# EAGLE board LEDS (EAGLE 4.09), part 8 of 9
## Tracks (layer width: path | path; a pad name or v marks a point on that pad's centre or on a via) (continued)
N$X.3143  (via drill 0.2)  (1 unrouted) (continued)
  other vias: 92.89,75.03
N$X.3144  (via drill 0.2)  (1 unrouted)
  Bottom 0.2: 94.72,74.97 94.18,75.51 93.83,75.51
  other vias: 94.68,74.95
N$X.3145  (via drill 0.2)  (1 unrouted)
  Bottom 0.2: 96.47,75 95.92,75.54 95.57,75.54
  other vias: 96.42,74.98
N$X.3146  (via drill 0.2)  (1 unrouted)
  Bottom 0.2: 98.2,75.05 97.66,75.6 97.31,75.6
  other vias: 98.16,75.03
N$X.3147  (via drill 0.2)  (1 unrouted)
  Bottom 0.2: 99.97,75.02 99.42,75.57 99.08,75.57
  other vias: 99.92,75
N$X.3148  (via drill 0.2)  (1 unrouted)
  Bottom 0.2: 101.63,75.02 101.08,75.57 100.73,75.57
  other vias: 101.58,75
N$X.3149  (via drill 0.2)  (1 unrouted)
  Bottom 0.2: 103.39,75 102.85,75.54 102.5,75.54
  other vias: 103.35,74.98
N$X.3150  (via drill 0.2)  (1 unrouted)
  Bottom 0.2: 105.25,75.02 104.7,75.57 104.35,75.57
  other vias: 105.2,75
N$X.3151  (via drill 0.2)  (1 unrouted)
  Bottom 0.2: 106.93,75.02 106.39,75.57 106.03,75.57
  other vias: 106.89,75
N$X.3152  (via drill 0.2)  (1 unrouted)
  Bottom 0.2: 106.84,72.48 106.3,73.03 105.95,73.03
  other vias: 106.8,72.46
N$X.3153  (via drill 0.2)  (1 unrouted)
  Bottom 0.2: 105.11,72.48 104.56,73.03 104.21,73.03
  other vias: 105.06,72.46
N$X.3154  (via drill 0.2)  (1 unrouted)
  Bottom 0.2: 103.48,72.46 102.94,73 102.58,73
  other vias: 103.44,72.44
N$X.3155  (via drill 0.2)  (1 unrouted)
  Bottom 0.2: 101.63,72.4 101.08,72.95 100.73,72.95
  other vias: 101.67,72.42
N$X.3156  (via drill 0.2)  (1 unrouted)
  Bottom 0.2: 99.97,72.46 99.42,73 99.08,73
  other vias: 99.92,72.44
N$X.3157  (via drill 0.2)  (1 unrouted)
  Bottom 0.2: 98.23,72.43 97.69,72.97 97.33,72.97
  other vias: 98.19,72.41
N$X.3158  (via drill 0.2)  (1 unrouted)
  Bottom 0.2: 96.41,72.4 95.86,72.95 95.52,72.95
  other vias: 96.47,72.42
N$X.3159  (via drill 0.2)  (1 unrouted)
  Bottom 0.2: 94.7,72.43 94.16,72.97 93.8,72.97
  other vias: 94.66,72.41
N$X.3160  (via drill 0.2)  (1 unrouted)
  Bottom 0.2: 93.04,72.4 92.5,72.95 92.14,72.95
  other vias: 93,72.38
N$X.3161  (via drill 0.2)  (1 unrouted)
  Bottom 0.2: 91.19,72.37 90.64,72.92 90.3,72.92
  other vias: 91.21,72.39
N$X.3162  (via drill 0.2)  (1 unrouted)
  Bottom 0.2: 89.48,72.4 88.94,72.95 88.58,72.95
  other vias: 89.44,72.38
N$X.3163  (via drill 0.2)  (1 unrouted)
  Bottom 0.2: 87.63,72.4 87.08,72.95 86.73,72.95
  other vias: 87.65,72.42
N$X.3164  (via drill 0.2)  (1 unrouted)
  Bottom 0.2: 85.94,72.43 85.4,72.97 85.05,72.97
  other vias: 85.9,72.41
N$X.3165  (via drill 0.2)  (1 unrouted)
  Bottom 0.2: v84.18,72.4 83.64,72.95 83.28,72.95
N$X.3166  (via drill 0.2)  (1 unrouted)
  Bottom 0.2: 84.18,69.81 83.64,70.35 83.28,70.35
  other vias: 84.14,69.79
N$X.3167  (via drill 0.2)  (1 unrouted)
  Bottom 0.2: 85.89,69.83 85.34,70.38 85,70.38
  other vias: 85.84,69.81
N$X.3168  (via drill 0.2)  (1 unrouted)
  Bottom 0.2: 87.69,69.83 87.14,70.38 86.79,70.38
  other vias: 87.64,69.81
N$X.3169  (via drill 0.2)  (1 unrouted)
  Bottom 0.2: 89.45,69.86 88.91,70.41 88.55,70.41
  other vias: 89.41,69.84
N$X.3170  (via drill 0.2)  (1 unrouted)
  Bottom 0.2: 91.16,69.78 90.62,70.32 90.27,70.32
  other vias: 91.18,69.8
N$X.3171  (via drill 0.2)  (1 unrouted)
  Bottom 0.2: 93.04,69.83 92.5,70.38 92.14,70.38
  other vias: 93,69.81
N$X.3172  (via drill 0.2)  (1 unrouted)
  Bottom 0.2: 94.78,69.83 94.23,70.38 93.89,70.38
  other vias: 94.73,69.81
N$X.3173  (via drill 0.2)  (1 unrouted)
  Bottom 0.2: 96.49,69.86 95.94,70.41 95.59,70.41
  other vias: 96.44,69.84
N$X.3174  (via drill 0.2)  (1 unrouted)
  Bottom 0.2: 98.28,69.83 97.74,70.38 97.39,70.38
  other vias: 98.24,69.81
N$X.3175  (via drill 0.2)  (1 unrouted)
  Bottom 0.2: 100.05,69.89 99.51,70.43 99.16,70.43
  other vias: 99.99,69.83
N$X.3176  (via drill 0.2)  (1 unrouted)
  Bottom 0.2: 101.63,69.92 101.08,70.46 100.73,70.46
  other vias: 101.63,69.81
N$X.3177  (via drill 0.2)  (1 unrouted)
  Bottom 0.2: 103.42,69.86 102.88,70.41 102.53,70.41
  other vias: 103.38,69.84
N$X.3178  (via drill 0.2)  (1 unrouted)
  Bottom 0.2: 105.3,69.83 104.75,70.38 104.41,70.38
  other vias: 105.17,69.83
N$X.3179  (via drill 0.2)  (1 unrouted)
  Bottom 0.2: 106.9,69.86 106.36,70.41 106,70.41
  other vias: 106.86,69.84
N$X.3180  (via drill 0.2)  (1 unrouted)
  Bottom 0.2: 106.93,67.18 106.39,67.73 106.03,67.73
  other vias: 106.89,67.16
N$X.3181  (via drill 0.2)  (1 unrouted)
  Bottom 0.2: 105.19,67.24 104.64,67.78 104.3,67.78
  other vias: 105.14,67.22
N$X.3182  (via drill 0.2)  (1 unrouted)
  Bottom 0.2: 103.5,67.24 102.96,67.78 102.61,67.78
  other vias: 103.46,67.17
N$X.3183  (via drill 0.2)  (1 unrouted)
  Bottom 0.2: 101.74,67.18 101.19,67.73 100.84,67.73
  other vias: 101.69,67.16
N$X.3184  (via drill 0.2)  (1 unrouted)
  Bottom 0.2: 100,67.18 99.45,67.73 99.11,67.73
  other vias: 99.95,67.16
N$X.3185  (via drill 0.2)  (1 unrouted)
  Bottom 0.2: 98.26,67.21 97.72,67.76 97.36,67.76
  other vias: 98.22,67.19
N$X.3186  (via drill 0.2)  (1 unrouted)
  Bottom 0.2: 96.47,67.24 95.92,67.78 95.57,67.78
  other vias: 96.42,67.22
N$X.3187  (via drill 0.2)  (1 unrouted)
  Bottom 0.2: 94.7,67.24 94.16,67.78 93.8,67.78
  other vias: 94.66,67.22
N$X.3188  (via drill 0.2)  (1 unrouted)
  Bottom 0.2: 92.96,67.21 92.41,67.76 92.06,67.76
  other vias: 92.91,67.19
N$X.3189  (via drill 0.2)  (1 unrouted)
  Bottom 0.2: 91.19,67.21 90.64,67.76 90.3,67.76
  other vias: 91.14,67.19
N$X.3190  (via drill 0.2)  (1 unrouted)
  Bottom 0.2: 89.48,67.21 88.94,67.76 88.58,67.76
  other vias: 89.44,67.19
N$X.3191  (via drill 0.2)  (1 unrouted)
  Bottom 0.2: 87.69,67.24 87.14,67.78 86.79,67.78
  other vias: 87.64,67.22
N$X.3192  (via drill 0.2)  (1 unrouted)
  Bottom 0.2: 85.97,67.21 85.43,67.76 85.08,67.76
  other vias: 85.93,67.19
N$X.3193  (via drill 0.2)  (1 unrouted)
  Bottom 0.2: 84.23,67.27 83.69,67.81 83.34,67.81
  other vias: 84.19,67.2
N$X.3194  (via drill 0.2)  (1 unrouted)
  Bottom 0.2: 84.23,64.62 83.69,65.16 83.34,65.16
  other vias: 84.19,64.6
N$X.3195  (via drill 0.2)  (1 unrouted)
  Bottom 0.2: 85.89,64.64 85.34,65.19 85,65.19
  other vias: 85.84,64.62
N$X.3196  (via drill 0.2)  (1 unrouted)
  Bottom 0.2: 87.77,64.59 87.22,65.13 86.87,65.13
  other vias: 87.72,64.57
N$X.3197  (via drill 0.2)  (1 unrouted)
  Bottom 0.2: 89.42,64.64 88.88,65.19 88.53,65.19
  other vias: 89.38,64.62
N$X.3198  (via drill 0.2)  (1 unrouted)
  Bottom 0.2: 91.28,64.62 90.73,65.16 90.38,65.16
  other vias: 91.23,64.6
N$X.3199  (via drill 0.2)  (1 unrouted)
  Bottom 0.2: 92.93,64.67 92.39,65.22 92.03,65.22
  other vias: 92.89,64.65
N$X.3200  (via drill 0.2)  (1 unrouted)
  Bottom 0.2: 94.72,64.59 94.18,65.13 93.83,65.13
  other vias: 94.68,64.57
N$X.3201  (via drill 0.2)  (1 unrouted)
  Bottom 0.2: 96.44,64.59 95.89,65.13 95.54,65.13
  other vias: 96.39,64.57
N$X.3202  (via drill 0.2)  (1 unrouted)
  Bottom 0.2: 98.26,64.59 97.72,65.13 97.36,65.13
  other vias: 98.22,64.57
N$X.3203  (via drill 0.2)  (1 unrouted)
  Bottom 0.2: 99.97,64.67 99.42,65.22 99.08,65.22
  other vias: 99.95,64.57
N$X.3204  (via drill 0.2)  (1 unrouted)
  Bottom 0.2: 101.69,64.64 101.14,65.19 100.79,65.19
  other vias: 101.66,64.58
N$X.3205  (via drill 0.2)  (1 unrouted)
  Bottom 0.2: 103.45,64.64 102.91,65.19 102.55,65.19
  other vias: 103.36,64.56
N$X.3206  (via drill 0.2)  (1 unrouted)
  Bottom 0.2: 105.16,64.64 104.61,65.19 104.27,65.19
  other vias: 105.11,64.54
N$X.3207  (via drill 0.2)  (1 unrouted)
  Bottom 0.2: 106.9,64.59 106.36,65.13 106,65.13
  other vias: 106.86,64.57
N$X.3208  (via drill 0.2)  (1 unrouted)
  Bottom 0.2: 106.9,61.94 106.36,62.48 106,62.48
  other vias: 106.86,61.92
N$X.3209  (via drill 0.2)  (1 unrouted)
  Bottom 0.2: 105.22,61.99 104.67,62.54 104.32,62.54
  other vias: 105.17,61.97
N$X.3210  (via drill 0.2)  (1 unrouted)
  Bottom 0.2: 103.42,61.96 102.88,62.51 102.53,62.51
  other vias: 103.38,61.94
N$X.3211  (via drill 0.2)  (1 unrouted)
  Bottom 0.2: 101.6,61.99 101.05,62.54 100.7,62.54
  other vias: 101.55,61.97
N$X.3212  (via drill 0.2)  (1 unrouted)
  Bottom 0.2: 99.91,61.96 99.37,62.51 99.02,62.51
  other vias: 99.87,61.94
N$X.3213  (via drill 0.2)  (1 unrouted)
  Bottom 0.2: 98.23,61.96 97.69,62.51 97.33,62.51
  other vias: 98.19,61.94
N$X.3214  (via drill 0.2)  (1 unrouted)
  Bottom 0.2: 96.49,62.02 95.94,62.56 95.59,62.56
  other vias: 96.44,61.95
N$X.3215  (via drill 0.2)  (1 unrouted)
  Bottom 0.2: 94.72,62.02 94.18,62.56 93.83,62.56
  other vias: 94.72,61.91
N$X.3216  (via drill 0.2)  (1 unrouted)
  Bottom 0.2: 92.98,62.05 92.44,62.59 92.09,62.59
  other vias: 92.94,61.97
N$X.3217  (via drill 0.2)  (1 unrouted)
  Bottom 0.2: 91.22,61.94 90.67,62.48 90.33,62.48
  other vias: 91.17,61.92
N$X.3218  (via drill 0.2)  (1 unrouted)
  Bottom 0.2: 89.5,62.05 88.96,62.59 88.61,62.59
  other vias: 89.41,61.97
N$X.3219  (via drill 0.2)  (1 unrouted)
  Bottom 0.2: 87.63,62.02 87.08,62.56 86.73,62.56
  other vias: 87.58,62
N$X.3220  (via drill 0.2)  (1 unrouted)
  Bottom 0.2: 85.89,62.02 85.34,62.56 85,62.56
  other vias: 85.89,61.95
N$X.3221  (via drill 0.2)  (1 unrouted)
  Bottom 0.2: 84.18,61.96 83.64,62.51 83.28,62.51
  other vias: 84.14,61.94
N$X.3222  (via drill 0.2)  (1 unrouted)
  Bottom 0.2: 108.64,75.05 108.09,75.6 107.75,75.6
  other vias: 108.59,75.03
N$X.3223  (via drill 0.2)  (1 unrouted)
  Bottom 0.2: 108.67,72.46 108.12,73 107.78,73
  other vias: 108.62,72.44
N$X.3224  (via drill 0.2)  (1 unrouted)
  Bottom 0.2: 108.64,69.94 108.09,70.49 107.75,70.49
  other vias: 108.59,69.92
N$X.3225  (via drill 0.2)  (1 unrouted)
  Bottom 0.2: 108.64,67.27 108.09,67.81 107.75,67.81
  other vias: 108.59,67.25
N$X.3226  (via drill 0.2)  (1 unrouted)
  Bottom 0.2: 108.61,64.59 108.07,65.13 107.72,65.13
  other vias: 108.57,64.57
N$X.3227  (via drill 0.2)  (1 unrouted)
  Bottom 0.2: 108.67,61.99 108.12,62.54 107.78,62.54
  other vias: 108.62,61.97
N$X.3228  (via drill 0.2)  (1 unrouted)
  Bottom 0.2: 110.38,61.99 109.83,62.54 109.48,62.54
  other vias: 110.36,61.93
N$X.3229  (via drill 0.2)  (1 unrouted)
  Bottom 0.2: 110.36,64.64 109.81,65.19 109.46,65.19
  other vias: 110.35,64.54
N$X.3230  (via drill 0.2)  (1 unrouted)
  Bottom 0.2: 110.38,67.29 109.83,67.84 109.48,67.84
  other vias: 110.33,67.21
N$X.3231  (via drill 0.2)  (1 unrouted)
  Bottom 0.2: 110.33,69.92 109.78,70.46 109.43,70.46
  other vias: 110.28,69.9
N$X.3232  (via drill 0.2)  (1 unrouted)
  Bottom 0.2: 110.36,72.51 109.81,73.06 109.46,73.06
  other vias: 110.31,72.49
N$X.3233  (via drill 0.2)  (1 unrouted)
  Bottom 0.2: 110.41,75.11 109.86,75.65 109.52,75.65
  other vias: 110.36,75
N$X.3234  (via drill 0.2)  (1 unrouted)
  Bottom 0.2: 112.12,75.05 111.58,75.6 111.22,75.6
  other vias: 112.08,75.03
N$X.3235  (via drill 0.2)  (1 unrouted)
  Bottom 0.2: 112.14,72.51 111.6,73.06 111.25,73.06
  other vias: 112.1,72.49
N$X.3236  (via drill 0.2)  (1 unrouted)
  Bottom 0.2: 112.06,69.78 111.52,70.32 111.17,70.32
  other vias: 112.02,69.76
N$X.3237  (via drill 0.2)  (1 unrouted)
  Bottom 0.2: 112.12,67.27 111.58,67.81 111.22,67.81
  other vias: 112.08,67.25
N$X.3238  (via drill 0.2)  (1 unrouted)
  Bottom 0.2: 112.12,64.59 111.58,65.13 111.22,65.13
  other vias: 112.08,64.57
N$X.3239  (via drill 0.2)  (1 unrouted)
  Bottom 0.2: 112.23,61.96 111.69,62.51 111.33,62.51
  other vias: 112.19,61.94
N$X.3242  (via drill 0.2)  (1 unrouted)
  Bottom 0.2: 113.95,67.19 113.67,67.92 113.33,67.92
  other vias: 113.96,67.17
N$X.3246  (via drill 0.2)  (1 unrouted)
  Bottom 0.2: 19.4,72.48 18.86,73.03 18.51,73.03
  other vias: 19.36,72.46
N$X.3247  (via drill 0.2)  (1 unrouted)
  Bottom 0.2: 17.63,72.46 17.09,73 16.74,73
  other vias: 17.59,72.44
N$X.3248  (via drill 0.2)  (1 unrouted)
  Bottom 0.2: 15.87,72.46 15.33,73 14.98,73
  other vias: 15.83,72.44
N$X.3249  (via drill 0.2)  (1 unrouted)
  Bottom 0.2: 14.16,72.4 13.62,72.95 13.27,72.95
  other vias: 14.12,72.38
N$X.3250  (via drill 0.2)  (1 unrouted)
  Bottom 0.2: 12.31,72.48 11.77,73.03 11.42,73.03
  other vias: 12.27,72.46
N$X.3251  (via drill 0.2)  (1 unrouted)
  Bottom 0.2: 10.6,72.4 10.05,72.95 9.7,72.95
  other vias: 10.55,72.38
N$X.3252  (via drill 0.2)  (1 unrouted)
  Bottom 0.2: 8.83,72.4 8.29,72.95 7.93,72.95
  other vias: 8.85,72.42
N$X.3253  (via drill 0.2)  (1 unrouted)
  Bottom 0.2: 7.04,72.46 6.49,73 6.14,73
  other vias: 6.99,72.44
N$X.3254  (via drill 0.2)  (1 unrouted)
  Bottom 0.2: 5.35,72.43 4.8,72.97 4.46,72.97
  other vias: 5.3,72.41
N$X.3255  (via drill 0.2)  (1 unrouted)
  Bottom 0.2: 3.56,72.43 3.01,72.97 2.66,72.97
  other vias: 3.51,72.41
N$X.3256  (via drill 0.2)  (1 unrouted)
  Bottom 0.2: 3.5,75.02 2.96,75.57 2.6,75.57
  other vias: 3.46,75
N$X.3257  (via drill 0.2)  (1 unrouted)
  Bottom 0.2: 5.29,74.97 4.75,75.51 4.4,75.51
  other vias: 5.25,74.95
N$X.3258  (via drill 0.2)  (1 unrouted)
  Bottom 0.2: 7.09,75 6.54,75.54 6.19,75.54
  other vias: 7.06,74.91
N$X.3259  (via drill 0.2)  (1 unrouted)
  Bottom 0.2: 8.86,75 8.31,75.54 7.96,75.54
  other vias: 8.81,74.92
N$X.3260  (via drill 0.2)  (1 unrouted)
  Bottom 0.2: 10.68,74.94 10.13,75.49 9.79,75.49
  other vias: 10.63,74.94
N$X.3261  (via drill 0.2)  (1 unrouted)
  Bottom 0.2: 12.45,75 11.9,75.54 11.55,75.54
  other vias: 12.32,74.96
N$X.3262  (via drill 0.2)  (1 unrouted)
  Bottom 0.2: 14.27,74.97 13.73,75.51 13.38,75.51
  other vias: 14.16,74.95
N$X.3263  (via drill 0.2)  (1 unrouted)
  Bottom 0.2: 15.93,75 15.38,75.54 15.03,75.54
  other vias: 16.05,74.92
N$X.3264  (via drill 0.2)  (1 unrouted)
  Bottom 0.2: 17.66,75 17.12,75.54 16.77,75.54
  other vias: 17.81,74.92
N$X.3265  (via drill 0.2)  (1 unrouted)
  Bottom 0.2: 19.48,74.91 18.94,75.46 18.59,75.46
  other vias: 19.55,74.94
N$X.3266  (via drill 0.2)  (1 unrouted)
  Bottom 0.2: 21.22,74.97 20.68,75.51 20.33,75.51
  other vias: 21.18,74.95
N$X.3267  (via drill 0.2)  (4 unrouted)
  Top 0.8: 23,84.96 23.19,84.76 23.19,1.74
  Bottom 0.2: 23.05,74.97 22.5,75.51 22.15,75.51 | 23.13,1.75 22.11,2.32 21.75,2.32
  other vias: 23.22,74.92 23.18,1.74
N$X.3268  (via drill 0.2)  (1 unrouted)
  Bottom 0.2: 24.76,75 24.21,75.54 23.86,75.54
  other vias: 25.02,74.92
N$X.3269  (via drill 0.2)  (4 unrouted)
  Top 0.8: 26.48,84.99 26.84,84.63 26.84,1.78
  Bottom 0.2: 26.47,75.05 25.92,75.6 25.57,75.6 | 26.74,1.74 26.51,2.3 25.59,2.35
  other vias: 26.87,74.93 26.76,1.74
N$X.3270  (via drill 0.2)  (1 unrouted)
  Bottom 0.2: 26.79,77.46 25.94,78.12 25.57,78.14
  other vias: 26.82,77.48
N$X.3271  (via drill 0.2)  (1 unrouted)
  Bottom 0.2: v25.01,77.49 24.16,78.22 23.81,78.22
N$X.3272  (via drill 0.2)  (1 unrouted)
  Bottom 0.2: 23.22,77.47 22.42,78.17 22.07,78.17
  other vias: 23.22,77.5
N$X.3273  (via drill 0.2)  (1 unrouted)
  Bottom 0.2: 21.17,77.62 20.62,78.17 20.27,78.17
  other vias: 21.29,77.5
N$X.3274  (via drill 0.2)  (1 unrouted)
  Bottom 0.2: 19.46,77.62 18.91,78.17 18.56,78.17
  other vias: 19.6,77.49
N$X.3275  (via drill 0.2)  (1 unrouted)
  Bottom 0.2: 17.66,77.59 17.12,78.14 16.77,78.14
  other vias: 17.76,77.51
N$X.3276  (via drill 0.2)  (1 unrouted)
  Bottom 0.2: 15.87,77.59 15.33,78.14 14.98,78.14
  other vias: 16.04,77.52
N$X.3277  (via drill 0.2)  (1 unrouted)
  Bottom 0.2: 14.13,77.62 13.59,78.17 13.24,78.17
  other vias: 14.04,77.52
N$X.3278  (via drill 0.2)  (1 unrouted)
  Bottom 0.2: 12.28,77.62 11.74,78.17 11.38,78.17
  other vias: 12.3,77.52
N$X.3279  (via drill 0.2)  (1 unrouted)
  Bottom 0.2: 10.6,77.62 10.05,78.17 9.7,78.17
  other vias: 10.57,77.52
N$X.3280  (via drill 0.2)  (1 unrouted)
  Bottom 0.2: 8.86,77.57 8.31,78.11 7.96,78.11
  other vias: 8.82,77.48
N$X.3281  (via drill 0.2)  (1 unrouted)
  Bottom 0.2: 7.09,77.57 6.54,78.11 6.19,78.11
  other vias: 7.04,77.48
N$X.3282  (via drill 0.2)  (1 unrouted)
  Bottom 0.2: 5.21,77.59 4.67,78.14 4.31,78.14
  other vias: 5.17,77.57
N$X.3283  (via drill 0.2)  (1 unrouted)
  Bottom 0.2: 3.42,77.59 2.88,78.14 2.53,78.14
  other vias: 3.38,77.57
N$X.3284  (via drill 0.2)  (1 unrouted)
  Bottom 0.2: 3.51,80.05 2.96,80.59 2.58,80.68
  other vias: 3.43,80.11
N$X.3285  (via drill 0.2)  (1 unrouted)
  Bottom 0.2: 5.21,80.13 4.67,80.68 4.31,80.68
  other vias: 5.17,80.11
N$X.3286  (via drill 0.2)  (1 unrouted)
  Bottom 0.2: 7.09,80.08 6.54,80.62 6.19,80.62
  other vias: 7.04,80.06
N$X.3287  (via drill 0.2)  (1 unrouted)
  Bottom 0.2: 8.88,80.16 8.34,80.71 7.99,80.71
  other vias: 8.86,80.08
N$X.3288  (via drill 0.2)  (1 unrouted)
  Bottom 0.2: 10.65,80.16 10.11,80.71 9.76,80.71
  other vias: 10.61,80.14
N$X.3289  (via drill 0.2)  (1 unrouted)
  Bottom 0.2: 12.37,80.16 11.82,80.71 11.47,80.71
  other vias: 12.32,80.14
N$X.3290  (via drill 0.2)  (1 unrouted)
  Bottom 0.2: 14.16,80.13 13.62,80.68 13.27,80.68
  other vias: 14.12,80.11
N$X.3291  (via drill 0.2)  (1 unrouted)
  Bottom 0.2: 15.9,80.16 15.36,80.71 15.01,80.71
  other vias: 15.94,80.08
N$X.3292  (via drill 0.2)  (1 unrouted)
  Bottom 0.2: 17.8,80.13 17.26,80.68 16.91,80.68
  other vias: 17.82,80.08
N$X.3293  (via drill 0.2)  (1 unrouted)
  Bottom 0.2: 19.43,80.13 18.88,80.68 18.54,80.68
  other vias: 19.55,80.07
N$X.3294  (via drill 0.2)  (1 unrouted)
  Bottom 0.2: 21.14,80.08 20.6,80.62 20.25,80.62
  other vias: 21.42,80.08
N$X.3295  (via drill 0.2)  (1 unrouted)
  Bottom 0.2: 23.2,80.11 22.65,80.65 22.1,80.65
  other vias: 23.25,80.04
N$X.3296  (via drill 0.2)  (1 unrouted)
  Bottom 0.2: 25,80.1 24.46,80.65 23.89,80.62
  other vias: 25.02,80.08
N$X.3297  (via drill 0.2)  (1 unrouted)
  Bottom 0.2: 26.74,80.1 26.19,80.64 25.57,80.65
  other vias: 26.76,80.09
N$X.3298  (via drill 0.2)  (1 unrouted)
  Bottom 0.2: 26.78,82.67 25.92,83.25 25.57,83.25
  other vias: 26.8,82.68
N$X.3299  (via drill 0.2)  (1 unrouted)
  Bottom 0.2: 25.04,82.64 24.19,83.22 23.84,83.22
  other vias: 25.01,82.66
N$X.3300  (via drill 0.2)  (1 unrouted)
  Bottom 0.2: 23.17,82.67 22.42,83.22 22.07,83.22
  other vias: 23.2,82.65
N$X.3301  (via drill 0.2)  (1 unrouted)
  Bottom 0.2: 21.25,82.7 20.71,83.25 20.36,83.25
  other vias: 21.42,82.65
N$X.3302  (via drill 0.2)  (1 unrouted)
  Bottom 0.2: 19.4,82.76 18.86,83.3 18.51,83.3
  other vias: 19.53,82.67
N$X.3303  (via drill 0.2)  (1 unrouted)
  Bottom 0.2: 17.63,82.78 17.09,83.33 16.74,83.33
  other vias: 17.63,82.68
N$X.3304  (via drill 0.2)  (1 unrouted)
  Bottom 0.2: 15.87,82.7 15.33,83.25 14.98,83.25
  other vias: 16.01,82.68
N$X.3305  (via drill 0.2)  (1 unrouted)
  Bottom 0.2: 14.11,82.73 13.56,83.27 13.21,83.27
  other vias: 14.06,82.71
N$X.3306  (via drill 0.2)  (1 unrouted)
  Bottom 0.2: 12.39,82.76 11.85,83.3 11.5,83.3
  other vias: 12.35,82.74
N$X.3307  (via drill 0.2)  (1 unrouted)
  Bottom 0.2: 10.57,82.84 10.03,83.38 9.68,83.38
  other vias: 10.57,82.69
N$X.3308  (via drill 0.2)  (1 unrouted)
  Bottom 0.2: 8.83,82.73 8.29,83.27 7.93,83.27
  other vias: 8.79,82.71
N$X.3309  (via drill 0.2)  (1 unrouted)
  Bottom 0.2: 6.98,82.76 6.43,83.3 6.08,83.3
  other vias: 7,82.67
N$X.3310  (via drill 0.2)  (1 unrouted)
  Bottom 0.2: 5.21,82.76 4.67,83.3 4.31,83.3
  other vias: 5.21,82.7
N$X.3311  (via drill 0.2)  (1 unrouted)
  Bottom 0.2: 3.42,82.76 2.88,83.3 2.53,83.3
  other vias: 3.38,82.74
N$X.3312  (via drill 0.2)  (1 unrouted)
  Bottom 0.2: 35.23,75.57 35.78,75.02
  other vias: 35.82,74.94
N$X.3313  (via drill 0.2)  (1 unrouted)
  Bottom 0.2: 37.49,75.07 36.86,75.6 36.51,75.6
  other vias: 37.58,74.95
N$X.3314
  Bottom 0.2: 38.1,75.57 38.39,75.61
N$X.3315
  Bottom 0.2: 39.87,75.54 40.11,75.54
N$X.3331
  Bottom 0.2: 31.2,78.11 30.85,78.11
N$X.3332
  Bottom 0.2: 29.38,78.17 29.03,78.17
N$X.3333  (via drill 0.2)  (1 unrouted)
  Bottom 0.2: 28.57,77.51 27.66,78.14 27.31,78.14
  other vias: 28.55,77.53
N$X.3334  (via drill 0.2)  (1 unrouted)
  Bottom 0.2: 28.59,80.09 27.66,80.68 27.31,80.68
  other vias: 28.62,80.07
N$X.3335
  Bottom 0.2: 29.43,80.68 29.08,80.68
N$X.3336
  Bottom 0.2: 31.31,80.65 30.96,80.65
N$X.3356
  Bottom 0.2: 32.97,83.25 32.62,83.25
N$X.3357
  Bottom 0.2: 31.2,83.27 30.85,83.27
N$X.3358
  Bottom 0.2: 29.4,83.27 29.05,83.27
N$X.3359  (via drill 0.2)  (1 unrouted)
  Bottom 0.2: 28.64,82.66 28.09,83.2 27.31,83.3
  other vias: 28.63,82.67
N$X.3372
  Bottom 0.2: 64.25,78.14 63.9,78.14
N$X.3373  (via drill 0.2)  (1 unrouted)
  Bottom 0.2: 66.59,77.59 66.05,78.14 65.69,78.14
  other vias: 66.55,77.57
N$X.3374  (via drill 0.2)  (1 unrouted)
  Bottom 0.2: 68.36,77.57 67.81,78.11 67.46,78.11
  other vias: 68.31,77.55
N$X.3375  (via drill 0.2)  (1 unrouted)
  Bottom 0.2: 69.96,77.57 69.41,78.11 69.06,78.11
  other vias: 69.91,77.55
N$X.3376  (via drill 0.2)  (1 unrouted)
  Bottom 0.2: 71.89,77.57 71.34,78.11 71,78.11
  other vias: 71.84,77.55
N$X.3377  (via drill 0.2)  (1 unrouted)
  Bottom 0.2: 73.66,77.57 73.11,78.11 72.77,78.11
  other vias: 73.61,77.55
N$X.3378  (via drill 0.2)  (1 unrouted)
  Bottom 0.2: 75.31,77.54 74.77,78.08 74.42,78.08
  other vias: 75.27,77.52
N$X.3379  (via drill 0.2)  (1 unrouted)
  Bottom 0.2: 75.2,80.13 74.66,80.68 74.31,80.68
  other vias: 75.33,80.09
N$X.3380  (via drill 0.2)  (1 unrouted)
  Bottom 0.2: 73.58,80.19 73.03,80.73 72.68,80.73
  other vias: 73.53,80.17
N$X.3381  (via drill 0.2)  (1 unrouted)
  Bottom 0.2: 71.78,80.13 71.23,80.68 70.89,80.68
  other vias: 71.73,80.11
N$X.3382  (via drill 0.2)  (1 unrouted)
  Bottom 0.2: 70.02,80.19 69.47,80.73 69.12,80.73
  other vias: 69.97,80.17
N$X.3383  (via drill 0.2)  (1 unrouted)
  Bottom 0.2: 68.3,80.13 67.75,80.68 67.41,80.68
  other vias: 68.25,80.11
N$X.3384  (via drill 0.2)  (1 unrouted)
  Bottom 0.2: 66.56,80.11 66.02,80.65 65.67,80.65
  other vias: 66.52,80.09
N$X.3398
  Bottom 0.2: 64.25,83.22 63.9,83.22
N$X.3399  (via drill 0.2)  (1 unrouted)
  Bottom 0.2: 66.62,82.7 66.08,83.25 65.72,83.25
  other vias: 66.58,82.68
N$X.3400  (via drill 0.2)  (1 unrouted)
  Bottom 0.2: 68.33,82.73 67.78,83.27 67.44,83.27
  other vias: 68.28,82.71
N$X.3401  (via drill 0.2)  (1 unrouted)
  Bottom 0.2: 70.09,82.73 69.55,83.27 69.2,83.27
  other vias: 70.05,82.71
N$X.3402  (via drill 0.2)  (1 unrouted)
  Bottom 0.2: 71.89,82.76 71.34,83.3 71,83.3
  other vias: 71.84,82.74
N$X.3403  (via drill 0.2)  (1 unrouted)
  Bottom 0.2: 73.63,82.67 73.08,83.22 72.73,83.22
  other vias: 73.65,82.67
N$X.3404  (via drill 0.2)  (1 unrouted)
  Bottom 0.2: 75.37,82.67 74.83,83.22 74.47,83.22
  other vias: 75.33,82.65
N$X.3405  (via drill 0.2)  (1 unrouted)
  Bottom 0.2: 77.11,82.73 76.56,83.27 76.22,83.27
  other vias: 77.06,82.71
N$X.3406  (via drill 0.2)  (1 unrouted)
  Bottom 0.2: 77.05,80.13 76.51,80.68 76.16,80.68
  other vias: 77.01,80.11
N$X.3407  (via drill 0.2)  (1 unrouted)
  Bottom 0.2: 77.11,77.51 76.56,78.05 76.22,78.05
  other vias: 77.06,77.49
N$X.3408  (via drill 0.2)  (1 unrouted)
  Bottom 0.2: 78.85,82.73 78.3,83.27 77.95,83.27
  other vias: 78.8,82.71
N$X.3409  (via drill 0.2)  (1 unrouted)
  Bottom 0.2: 78.88,80.13 78.33,80.68 77.98,80.68
  other vias: 78.83,80.11
N$X.3410  (via drill 0.2)  (1 unrouted)
  Bottom 0.2: 78.91,77.59 78.36,78.14 78.01,78.14
  other vias: 78.82,77.49
N$X.3411  (via drill 0.2)  (1 unrouted)
  Bottom 0.2: 80.64,77.62 80.1,78.17 79.75,78.17
  other vias: 80.6,77.5
N$X.3412  (via drill 0.2)  (1 unrouted)
  Bottom 0.2: 82.58,77.57 82.03,78.11 81.68,78.11
  other vias: 82.43,77.51
N$X.3413  (via drill 0.2)  (1 unrouted)
  Bottom 0.2: 84.04,77.59 83.5,78.14 83.14,78.14
  other vias: 84,77.57
N$X.3414  (via drill 0.2)  (1 unrouted)
  Bottom 0.2: 85.86,77.62 85.31,78.17 84.97,78.17
  other vias: 85.81,77.6
N$X.3415  (via drill 0.2)  (1 unrouted)
  Bottom 0.2: 87.63,77.59 87.08,78.14 86.73,78.14
  other vias: 87.58,77.57
N$X.3416  (via drill 0.2)  (1 unrouted)
  Bottom 0.2: 89.42,77.54 88.88,78.08 88.53,78.08
  other vias: 89.38,77.52
N$X.3417  (via drill 0.2)  (1 unrouted)
  Bottom 0.2: 91.2,77.57 90.67,78.14 90.33,78.14
  other vias: 91.17,77.47
N$X.3418  (via drill 0.2)  (1 unrouted)
  Bottom 0.2: 92.88,77.54 92.33,78.08 91.98,78.08
  other vias: 92.83,77.52
N$X.3419  (via drill 0.2)  (1 unrouted)
  Bottom 0.2: 94.7,77.51 94.16,78.05 93.8,78.05
  other vias: 94.66,77.49
N$X.3420  (via drill 0.2)  (1 unrouted)
  Bottom 0.2: 96.38,77.57 95.83,78.11 95.48,78.11
  other vias: 96.38,77.5
N$X.3421  (via drill 0.2)  (1 unrouted)
  Bottom 0.2: 98.06,77.59 97.52,78.14 97.17,78.14
  other vias: 98.02,77.57
N$X.3422  (via drill 0.2)  (1 unrouted)
  Bottom 0.2: 99.97,77.57 99.42,78.11 99.08,78.11
  other vias: 99.94,77.48
N$X.3423  (via drill 0.2)  (1 unrouted)
  Bottom 0.2: 99.86,80.11 99.31,80.65 98.97,80.65
  other vias: 99.81,80.09
N$X.3424  (via drill 0.2)  (1 unrouted)
  Bottom 0.2: 98.09,80.13 97.55,80.68 97.2,80.68
  other vias: 98.11,80.05
N$X.3425  (via drill 0.2)  (1 unrouted)
  Bottom 0.2: 96.38,80.19 95.83,80.73 95.48,80.73
  other vias: 96.33,80.17
N$X.3426  (via drill 0.2)  (1 unrouted)
  Bottom 0.2: 94.64,80.19 94.09,80.73 93.75,80.73
  other vias: 94.59,80.17
N$X.3427  (via drill 0.2)  (1 unrouted)
  Bottom 0.2: 92.91,80.13 92.36,80.68 92.01,80.68
  other vias: 92.86,80.11
N$X.3428  (via drill 0.2)  (1 unrouted)
  Bottom 0.2: 91.25,80.11 90.7,80.65 90.35,80.65
  other vias: 91.2,80.09
N$X.3429  (via drill 0.2)  (1 unrouted)
  Bottom 0.2: 89.45,80.11 88.91,80.65 88.55,80.65
  other vias: 89.41,80.09
N$X.3430  (via drill 0.2)  (1 unrouted)
  Bottom 0.2: 87.66,80.11 87.11,80.65 86.76,80.65
  other vias: 87.61,80.09
N$X.3431  (via drill 0.2)  (1 unrouted)
  Bottom 0.2: 85.94,80.08 85.4,80.62 85.05,80.62
  other vias: 85.9,80.06
N$X.3432  (via drill 0.2)  (1 unrouted)
  Bottom 0.2: 84.23,80.11 83.69,80.65 83.34,80.65
  other vias: 84.19,80.09
N$X.3433  (via drill 0.2)  (1 unrouted)
  Bottom 0.2: 82.39,80.16 81.84,80.71 81.49,80.71
  other vias: 82.34,80.14
N$X.3434  (via drill 0.2)  (1 unrouted)
  Bottom 0.2: 80.59,80.13 80.05,80.68 79.69,80.68
  other vias: 80.55,80.11
N$X.3435  (via drill 0.2)  (1 unrouted)
  Bottom 0.2: 80.64,82.7 80.1,83.25 79.75,83.25
  other vias: 80.6,82.68
N$X.3436  (via drill 0.2)  (1 unrouted)
  Bottom 0.2: 82.33,82.78 81.78,83.33 81.44,83.33
  other vias: 82.28,82.76
N$X.3437  (via drill 0.2)  (1 unrouted)
  Bottom 0.2: 84.18,82.78 83.64,83.33 83.28,83.33
  other vias: 84.14,82.76
N$X.3438  (via drill 0.2)  (1 unrouted)
  Bottom 0.2: 85.83,82.7 85.29,83.25 84.94,83.25
  other vias: 85.89,82.66
N$X.3439  (via drill 0.2)  (1 unrouted)
  Bottom 0.2: 87.6,82.73 87.05,83.27 86.7,83.27
  other vias: 87.55,82.71
N$X.3440  (via drill 0.2)  (1 unrouted)
  Bottom 0.2: 89.37,82.73 88.83,83.27 88.47,83.27
  other vias: 89.33,82.71
N$X.3441  (via drill 0.2)  (1 unrouted)
  Bottom 0.2: 91.19,82.76 90.64,83.3 90.3,83.3
  other vias: 91.14,82.74
N$X.3442  (via drill 0.2)  (1 unrouted)
  Bottom 0.2: 92.93,82.81 92.39,83.36 92.03,83.36
  other vias: 92.89,82.73
N$X.3443  (via drill 0.2)  (1 unrouted)
  Bottom 0.2: 94.61,82.73 94.07,83.27 93.72,83.27
  other vias: 94.57,82.71
N$X.3444  (via drill 0.2)  (1 unrouted)
  Bottom 0.2: 96.44,82.76 95.89,83.3 95.54,83.3
  other vias: 96.39,82.74
N$X.3445  (via drill 0.2)  (1 unrouted)
  Bottom 0.2: 98.15,82.76 97.61,83.3 97.25,83.3
  other vias: 98.11,82.74
N$X.3446  (via drill 0.2)  (1 unrouted)
  Bottom 0.2: 99.83,82.73 99.29,83.27 98.94,83.27
  other vias: 99.79,82.71
N$X.3447  (via drill 0.2)  (1 unrouted)
  Bottom 0.2: 101.66,82.76 101.11,83.3 100.76,83.3
  other vias: 101.61,82.74
N$X.3448  (via drill 0.2)  (1 unrouted)
  Bottom 0.2: 101.63,80.16 101.08,80.71 100.73,80.71
  other vias: 101.65,80.1
N$X.3449  (via drill 0.2)  (1 unrouted)
  Bottom 0.2: 101.66,77.54 101.11,78.08 100.76,78.08
  other vias: 101.61,77.52
N$X.3450  (via drill 0.2)  (1 unrouted)
  Bottom 0.2: 103.28,77.57 102.74,78.11 102.39,78.11
  other vias: 103.24,77.55
N$X.3451  (via drill 0.2)  (1 unrouted)
  Bottom 0.2: 103.39,80.11 102.85,80.65 102.5,80.65
  other vias: 103.35,80.09
N$X.3452  (via drill 0.2)  (1 unrouted)
  Bottom 0.2: 103.39,82.7 102.85,83.25 102.5,83.25
  other vias: 103.35,82.68
N$X.3453  (via drill 0.2)  (1 unrouted)
  Bottom 0.2: 105.19,82.81 104.64,83.36 104.3,83.36
  other vias: 105.19,82.67
N$X.3454  (via drill 0.2)  (1 unrouted)
  Bottom 0.2: 106.71,82.84 106.16,83.38 105.81,83.38
  other vias: 106.84,82.77
N$X.3455  (via drill 0.2)  (1 unrouted)
  Bottom 0.2: 105.08,80.11 104.53,80.65 104.19,80.65
  other vias: 105.18,80.07
N$X.3456  (via drill 0.2)  (1 unrouted)
  Bottom 0.2: 106.88,80.13 106.33,80.68 105.98,80.68
  other vias: 106.83,80.11
N$X.3457  (via drill 0.2)  (1 unrouted)
  Bottom 0.2: 108.47,80.16 107.93,80.71 107.58,80.71
  other vias: 108.43,80.14
N$X.3458  (via drill 0.2)  (1 unrouted)
  Bottom 0.2: 110.19,80.19 109.64,80.73 109.29,80.73
  other vias: 110.14,80.17
N$X.3459  (via drill 0.2)  (1 unrouted)
  Bottom 0.2: 112.12,80.11 111.58,80.65 111.22,80.65
  other vias: 112.08,80.09
N$X.3460  (via drill 0.2)  (1 unrouted)
  Bottom 0.2: 112.12,82.76 111.58,83.3 111.22,83.3
  other vias: 112.08,82.74
N$X.3461  (via drill 0.2)  (1 unrouted)
  Bottom 0.2: 110.27,82.76 109.72,83.3 109.38,83.3
  other vias: 110.22,82.74
N$X.3462  (via drill 0.2)  (1 unrouted)
  Bottom 0.2: 108.53,82.73 107.98,83.27 107.64,83.27
  other vias: 108.48,82.71
N$X.3463  (via drill 0.2)  (1 unrouted)
  Bottom 0.2: 108.64,77.54 108.09,78.08 107.75,78.08
  other vias: 108.59,77.52
N$X.3464  (via drill 0.2)  (1 unrouted)
  Bottom 0.2: 110.27,77.54 109.72,78.08 109.38,78.08
  other vias: 110.22,77.52
N$X.3465  (via drill 0.2)  (1 unrouted)
  Bottom 0.2: 112.14,77.57 111.6,78.11 111.25,78.11
  other vias: 112.1,77.55
N$X.3469  (via drill 0.2)  (1 unrouted)
  Bottom 0.2: 106.88,77.54 106.33,78.08 105.98,78.08
  other vias: 106.83,77.52
N$X.3470  (via drill 0.2)  (1 unrouted)
  Bottom 0.2: v105.14,77.48 104.59,78.03 104.24,78.03
N$X.3476  (via drill 0.2)  (1 unrouted)
  Bottom 0.2: 12.22,9.64 11.68,10.18 11.33,10.18
  other vias: 12.36,9.57
N$X.3477  (via drill 0.2)  (1 unrouted)
  Bottom 0.2: 12.28,6.98 11.73,7.53 11.38,7.53
  other vias: 12.23,6.96
N$X.3478  (via drill 0.2)  (1 unrouted)
  Bottom 0.2: 14.06,6.96 13.52,7.51 13.17,7.51
  other vias: 14.2,6.92
N$X.3479  (via drill 0.2)  (1 unrouted)
  Bottom 0.2: 14.04,9.64 13.5,10.18 13.15,10.18
  other vias: 14.11,9.57
N$X.3480  (via drill 0.2)  (1 unrouted)
  Bottom 0.2: 15.76,9.6 15.22,10.14 14.87,10.14
  other vias: 15.72,9.58
N$X.3481  (via drill 0.2)  (1 unrouted)
  Bottom 0.2: 17.77,9.55 16.84,10.14 16.49,10.14
  other vias: 17.79,9.57
N$X.3482  (via drill 0.2)  (1 unrouted)
  Bottom 0.2: 19.67,9.54 18.6,10.14 18.25,10.14
  other vias: 19.66,9.57
N$X.3483  (via drill 0.2)  (1 unrouted)
  Bottom 0.2: 21.39,9.53 20.36,10.14 20.01,10.14
  other vias: 21.39,9.57
N$X.3484  (via drill 0.2)  (1 unrouted)
  Bottom 0.2: 23.13,9.51 22.13,10.1 21.78,10.1
  other vias: 23.17,9.54
N$X.3485  (via drill 0.2)  (1 unrouted)
  Bottom 0.2: 24.98,9.55 23.81,10.12 23.88,10.15
  other vias: 24.96,9.55
N$X.3486  (via drill 0.2)  (1 unrouted)
  Bottom 0.2: 26.74,9.56 25.57,10.18 25.53,10.2
  other vias: 26.8,9.58
N$X.3487  (via drill 0.2)  (1 unrouted)
  Bottom 0.2: 16.01,6.92 15.2,7.55 14.85,7.55
  other vias: 15.99,6.93
N$X.3488  (via drill 0.2)  (1 unrouted)
  Bottom 0.2: v17.82,6.93 17.28,7.48 16.53,7.55
N$X.3489  (via drill 0.2)  (1 unrouted)
  Bottom 0.2: 19.65,6.95 19.11,7.5 18.25,7.51
  other vias: 19.61,6.94
N$X.3490  (via drill 0.2)  (1 unrouted)
  Bottom 0.2: 21.29,6.93 20.34,7.53 19.99,7.53
  other vias: 21.34,6.92
N$X.3491  (via drill 0.2)  (1 unrouted)
  Bottom 0.2: 23.18,6.87 22.08,7.55 21.73,7.55
  other vias: 23.19,6.91
N$X.3492  (via drill 0.2)  (1 unrouted)
  Bottom 0.2: 24.86,6.93 24.08,7.55 23.73,7.55
  other vias: 24.9,6.92
N$X.3493  (via drill 0.2)  (1 unrouted)
  Bottom 0.2: 26.64,6.94 25.97,7.53 25.62,7.53
  other vias: 26.67,6.95
N$X.3494  (via drill 0.2)  (1 unrouted)
  Bottom 0.2: 12.28,4.29 11.73,4.83 11.38,4.83
  other vias: 12.39,4.28
N$X.3495  (via drill 0.2)  (1 unrouted)
  Bottom 0.2: 14.11,4.33 13.56,4.87 13.21,4.87
  other vias: 14.06,4.31
N$X.3496  (via drill 0.2)  (1 unrouted)
  Bottom 0.2: 15.93,4.26 15.39,4.81 14.81,4.85
  other vias: 15.99,4.28
N$X.3497  (via drill 0.2)  (1 unrouted)
  Bottom 0.2: v17.76,4.29 17.21,4.84 16.47,4.89
N$X.3498  (via drill 0.2)  (1 unrouted)
  Bottom 0.2: 19.6,4.31 18.58,4.89 18.23,4.89
  other vias: 19.67,4.29
N$X.3499  (via drill 0.2)  (1 unrouted)
  Bottom 0.2: 21.59,4.29 20.4,4.87 20.05,4.87
  other vias: 21.59,4.3
N$X.3500  (via drill 0.2)  (1 unrouted)
  Bottom 0.2: 23.25,4.3 22.13,4.83 21.78,4.83
  other vias: 23.27,4.29
N$X.3501  (via drill 0.2)  (1 unrouted)
  Bottom 0.2: 24.98,4.32 23.89,4.85 23.87,4.86
  other vias: 24.99,4.29
N$X.3502  (via drill 0.2)  (1 unrouted)
  Bottom 0.2: 26.79,4.31 25.98,4.9 25.63,4.9
  other vias: 26.81,4.25
N$X.3503  (via drill 0.2)  (2 unrouted)
  Top 0.8: 10.43,1.73 10.74,2.04 10.74,84.95
  Bottom 0.2: 10.52,1.76 9.97,2.3 9.62,2.3
  other vias: 10.47,1.74
N$X.3504  (via drill 0.2)  (2 unrouted)
  Top 0.8: 12.4,84.89 12.25,84.74 12.25,1.73
  Bottom 0.2: 12.28,1.73 11.73,2.28 11.38,2.28
  other vias: 12.38,1.72
N$X.3505  (via drill 0.2)  (2 unrouted)
  Top 0.8: 14.06,1.73 14.11,1.79 14.11,84.89
  Bottom 0.2: 14,1.73 13.46,2.28 13.11,2.28
  other vias: 13.96,1.71
N$X.3506  (via drill 0.2)  (2 unrouted)
  Top 0.8: 16.03,84.89 15.93,84.64 15.93,1.89
  Bottom 0.2: 15.98,1.68 15.44,2.23 14.79,2.22
  other vias: 15.94,1.72
N$X.3507  (via drill 0.2)  (2 unrouted)
  Top 0.8: 17.38,1.68 17.69,1.99 17.69,84.95
  Bottom 0.2: 17.8,1.71 16.86,2.32 16.51,2.32
  other vias: 17.8,1.76
N$X.3508  (via drill 0.2)  (2 unrouted)
  Top 0.8: 19.5,84.95 19.56,84.37 19.56,1.52
  Bottom 0.2: 19.55,1.69 18.58,2.3 18.23,2.3
  other vias: 19.57,1.71
N$X.3509  (via drill 0.2)  (2 unrouted)
  Top 0.8: 20.9,1.68 21.26,2.04 21.26,84.89
  Bottom 0.2: 21.34,1.76 20.42,2.28 20.07,2.28
  other vias: 21.38,1.72
N$X.3511  (via drill 0.2)  (2 unrouted)
  Top 0.8: 24.82,1.74 24.82,84.96
  Bottom 0.2: 24.81,1.71 23.89,2.36 23.87,2.36
  other vias: 24.8,1.76
N$X.3513  (via drill 0.2)  (1 unrouted)
  Bottom 0.2: 30.42,9.51 29.84,10.19 29.14,10.21
  other vias: 30.44,9.55
N$X.3514  (via drill 0.2)  (1 unrouted)
  Bottom 0.2: 32.26,9.61 31.72,10.16 31.21,10.25
  other vias: 32.26,9.6
N$X.3515  (via drill 0.2)  (1 unrouted)
  Bottom 0.2: 34.05,9.54 33.51,10.08 33.02,10.12
  other vias: 34.03,9.56
N$X.3516
  Bottom 0.2: 34.38,10.1 34.91,10.14
N$X.3530
  Bottom 0.2: 35.2,7.66 34.85,7.66
N$X.3531  (via drill 0.2)  (1 unrouted)
  Bottom 0.2: 34.04,6.96 33.5,7.5 32.97,7.55
  other vias: 34.04,6.98
N$X.3532  (via drill 0.2)  (1 unrouted)
  Bottom 0.2: 32.26,6.98 31.72,7.53 31.15,7.57
  other vias: 32.24,6.98
N$X.3533  (via drill 0.2)  (1 unrouted)
  Bottom 0.2: 30.72,6.47 30.22,7.06 29.06,7.55
  other vias: 30.35,6.97
N$X.3534  (via drill 0.2)  (1 unrouted)
  Bottom 0.2: 30.4,4.36 29.89,4.9 29.43,4.88
  other vias: 30.42,4.32
N$X.3535  (via drill 0.2)  (1 unrouted)
  Bottom 0.2: 32.15,4.37 31.61,4.91 31.17,4.94
  other vias: 32.17,4.31
N$X.3536  (via drill 0.2)  (1 unrouted)
  Bottom 0.2: 34.05,4.35 33.55,4.87 32.73,4.87
  other vias: 34.05,4.29
N$X.3546
  Bottom 0.2: 35.03,2.38 34.68,2.38
N$X.3548  (via drill 0.2)  (2 unrouted)
  Top 0.8: 32.19,1.74 32.19,84.53 31.73,84.99
  Bottom 0.2: 32.22,1.78 31.67,2.32 31.26,2.36
  other vias: 32.19,1.78
N$X.3549  (via drill 0.2)  (4 unrouted)
  Top 0.8: 30,84.96 30.39,84.57 30.39,1.68
  Bottom 0.2: 30.37,1.73 29.82,2.28 29.26,2.3 | 30.37,74.98 29.82,75.52 29.05,75.54
  other vias: 30.39,1.71 30.41,74.93
N$X.3550  (via drill 0.2)  (1 unrouted)
  Bottom 0.2: 28.6,9.51 27.78,10.22 27.43,10.22
  other vias: 28.62,9.55
N$X.3551  (via drill 0.2)  (1 unrouted)
  Bottom 0.2: 28.41,6.96 27.87,7.5 27.41,7.54
  other vias: 28.45,6.97
N$X.3552  (via drill 0.2)  (1 unrouted)
  Bottom 0.2: 28.61,4.29 27.73,4.94 27.38,4.94
  other vias: 28.63,4.29
N$X.3553  (via drill 0.2)  (2 unrouted)
  Top 0.8: 28.67,1.74 28.67,84.53 28.24,84.96
  Bottom 0.2: 28.67,1.72 28.13,2.26 27.4,2.31
  other vias: 28.64,1.71
N$X.3560
  Bottom 0.2: 57.03,10.14 56.68,10.14
N$X.3561
  Bottom 0.2: 60.52,10.22 60.17,10.22
N$X.3562
  Bottom 0.2: 58.45,10.16 58.8,10.16
N$X.3573
  Bottom 0.2: 58.43,2.34 58.78,2.34
N$X.3574
  Bottom 0.2: 60.54,2.34 60.19,2.34
N$X.3575
  Bottom 0.2: 60.5,5 60.15,5
N$X.3576
  Bottom 0.2: 58.36,5 58.71,5
N$X.3577
  Bottom 0.2: 56.99,4.96 56.64,4.96
N$X.3588
  Bottom 0.2: 53.42,7.53 53.07,7.53
N$X.3590
  Bottom 0.2: 57.03,7.55 56.68,7.55
N$X.3591
  Bottom 0.2: 58.34,7.51 58.69,7.51
N$X.3592
  Bottom 0.2: 60.5,7.57 60.15,7.57
N$X.3593
  Bottom 0.2: 62.22,10.16 61.87,10.16
N$X.3594
  Bottom 0.2: 62.28,7.53 61.93,7.53
N$X.3595
  Bottom 0.2: 62.26,4.91 61.91,4.91
N$X.3596
  Bottom 0.2: 62.28,2.36 61.93,2.36
N$X.3597
  Bottom 0.2: 63.65,10.12 64,10.12
N$X.3598
  Bottom 0.2: 65.75,10.12 65.4,10.12
N$X.3599  (via drill 0.2)  (1 unrouted)
  Bottom 0.2: 67.99,9.6 67.45,10.14 67.1,10.14
  other vias: 67.95,9.58
N$X.3600  (via drill 0.2)  (1 unrouted)
  Bottom 0.2: 69.8,9.6 69.25,10.14 68.9,10.14
  other vias: 69.75,9.58
N$X.3601  (via drill 0.2)  (1 unrouted)
  Bottom 0.2: 71.6,9.58 71.06,10.12 70.71,10.12
  other vias: 71.56,9.56
N$X.3602  (via drill 0.2)  (1 unrouted)
  Bottom 0.2: 73.32,9.62 72.78,10.16 72.43,10.16
  other vias: 73.28,9.6
N$X.3603  (via drill 0.2)  (1 unrouted)
  Bottom 0.2: 75.02,9.62 74.48,10.16 74.13,10.16
  other vias: 74.98,9.6
N$X.3604  (via drill 0.2)  (1 unrouted)
  Bottom 0.2: 76.85,9.58 76.3,10.12 75.95,10.12
  other vias: 76.8,9.56
N$X.3605  (via drill 0.2)  (1 unrouted)
  Bottom 0.2: 78.67,9.58 78.13,10.12 77.78,10.12
  other vias: 78.63,9.56
N$X.3606  (via drill 0.2)  (1 unrouted)
  Bottom 0.2: 78.57,7.02 78.03,7.57 77.67,7.57
  other vias: 78.53,7
N$X.3607  (via drill 0.2)  (1 unrouted)
  Bottom 0.2: 76.85,6.94 76.3,7.49 75.95,7.49
  other vias: 76.82,6.98
N$X.3608  (via drill 0.2)  (1 unrouted)
  Bottom 0.2: 75.08,6.98 74.54,7.53 74.19,7.53
  other vias: 75.04,6.96
N$X.3609  (via drill 0.2)  (1 unrouted)
  Bottom 0.2: 73.3,6.96 72.76,7.51 72.41,7.51
  other vias: 73.26,6.94
N$X.3610  (via drill 0.2)  (1 unrouted)
  Bottom 0.2: 71.54,6.98 70.99,7.53 70.64,7.53
  other vias: 71.49,6.96
N$X.3611  (via drill 0.2)  (1 unrouted)
  Bottom 0.2: 69.82,7.07 69.27,7.61 68.92,7.61
  other vias: 69.73,7.02
N$X.3612  (via drill 0.2)  (1 unrouted)
  Bottom 0.2: 68.14,6.94 67.59,7.49 67.24,7.49
  other vias: 68.09,6.94
N$X.3613
  Bottom 0.2: 65.77,7.47 65.42,7.47
N$X.3614
  Bottom 0.2: 63.65,7.51 64,7.51
N$X.3615
  Bottom 0.2: 64.09,4.89 63.74,4.89
N$X.3616
  Bottom 0.2: 65.81,4.87 65.46,4.87
N$X.3617  (via drill 0.2)  (1 unrouted)
  Bottom 0.2: v68.03,4.31 67.49,4.85 67.14,4.85
N$X.3618  (via drill 0.2)  (1 unrouted)
  Bottom 0.2: 69.8,4.35 69.25,4.89 68.9,4.89
  other vias: 69.75,4.33
N$X.3619  (via drill 0.2)  (1 unrouted)
  Bottom 0.2: 71.54,4.37 70.99,4.91 70.64,4.91
  other vias: 71.49,4.35
N$X.3620  (via drill 0.2)  (1 unrouted)
  Bottom 0.2: 73.3,4.39 72.76,4.93 72.41,4.93
  other vias: 73.26,4.37
N$X.3621  (via drill 0.2)  (1 unrouted)
  Bottom 0.2: 75.04,4.37 74.5,4.91 74.15,4.91
  other vias: 75,4.35
N$X.3622  (via drill 0.2)  (1 unrouted)
  Bottom 0.2: 76.83,4.29 76.28,4.83 75.93,4.83
  other vias: 76.89,4.29
N$X.3623  (via drill 0.2)  (1 unrouted)
  Bottom 0.2: 78.61,4.29 78.07,4.83 77.72,4.83
  other vias: 78.63,4.29
N$X.3624  (via drill 0.2)  (2 unrouted)
  Top 0.8: 78.69,1.73 78.69,84.74
  Bottom 0.2: 78.69,1.8 78.15,2.34 77.8,2.34
  other vias: 78.61,1.74
N$X.3625  (via drill 0.2)  (2 unrouted)
  Top 0.8: 76.83,1.73 77.19,2.09 77.19,84.89
  Bottom 0.2: 76.85,1.78 76.3,2.32 75.95,2.32
  other vias: 76.8,1.76
N$X.3626  (via drill 0.2)  (2 unrouted)
  Top 0.8: 75.43,84.95 75.43,2.2 75.02,1.79
  Bottom 0.2: 75.08,1.8 74.54,2.34 74.19,2.34
  other vias: 75.04,1.78
N$X.3627  (via drill 0.2)  (2 unrouted)
  Top 0.8: 73.15,1.89 73.56,2.3 73.56,84.95
  Bottom 0.2: 73.26,1.82 72.72,2.36 72.36,2.36
  other vias: 73.22,1.8
N$X.3628  (via drill 0.2)  (2 unrouted)
  Top 0.8: 71.54,1.68 71.56,84.87
  Bottom 0.2: 71.54,1.78 70.99,2.32 70.64,2.32
  other vias: 71.49,1.76
N$X.3629  (via drill 0.2)  (2 unrouted)
  Top 0.8: 69.73,1.84 70.14,2.25 70.14,84.95
  Bottom 0.2: 69.86,1.8 69.31,2.34 68.96,2.34
  other vias: 69.81,1.78
N$X.3630  (via drill 0.2)  (2 unrouted)
  Top 0.8: 68.02,1.73 68.04,84.83
  Bottom 0.2: 68.07,1.76 67.53,2.3 67.18,2.3
  other vias: 68.03,1.74
N$X.3631
  Bottom 0.2: 65.81,2.28 65.46,2.28
N$X.3632
  Bottom 0.2: 63.72,2.28 64.07,2.28
N$X.3633  (via drill 0.2)  (1 unrouted)
  Bottom 0.2: 80.35,9.62 79.81,10.16 79.46,10.16
  other vias: 80.31,9.6
N$X.3634  (via drill 0.2)  (1 unrouted)
  Bottom 0.2: 80.31,7.02 79.77,7.57 79.42,7.57
  other vias: 80.27,7
N$X.3635  (via drill 0.2)  (1 unrouted)
  Bottom 0.2: 82.16,9.62 81.61,10.16 81.26,10.16
  other vias: 82.11,9.6
N$X.3636  (via drill 0.2)  (1 unrouted)
  Bottom 0.2: 83.94,9.58 83.4,10.12 83.05,10.12
  other vias: 83.9,9.56
N$X.3637  (via drill 0.2)  (1 unrouted)
  Bottom 0.2: 85.79,9.68 85.24,10.22 84.89,10.22
  other vias: 85.78,9.58
N$X.3638  (via drill 0.2)  (1 unrouted)
  Bottom 0.2: 87.63,9.64 87.09,10.18 86.74,10.18
  other vias: 87.59,9.62
N$X.3639  (via drill 0.2)  (1 unrouted)
  Bottom 0.2: 89.29,9.68 88.75,10.22 88.4,10.22
  other vias: 89.33,9.64
N$X.3640  (via drill 0.2)  (1 unrouted)
  Bottom 0.2: 91.02,9.72 90.47,10.27 90.12,10.27
  other vias: 91.01,9.66
N$X.3641  (via drill 0.2)  (1 unrouted)
  Bottom 0.2: 92.92,9.68 92.38,10.22 92.03,10.22
  other vias: 92.88,9.66
N$X.3642  (via drill 0.2)  (1 unrouted)
  Bottom 0.2: 94.54,9.68 94,10.22 93.65,10.22
  other vias: 94.54,9.64
N$X.3643  (via drill 0.2)  (1 unrouted)
  Bottom 0.2: 96.3,9.64 95.76,10.18 95.41,10.18
  other vias: 96.26,9.62
N$X.3644  (via drill 0.2)  (1 unrouted)
  Bottom 0.2: 96.33,7 95.78,7.55 95.43,7.55
  other vias: 96.28,6.98
N$X.3645  (via drill 0.2)  (1 unrouted)
  Bottom 0.2: 94.58,7.02 94.04,7.57 93.69,7.57
  other vias: 94.6,6.98
N$X.3646  (via drill 0.2)  (1 unrouted)
  Bottom 0.2: 92.72,7.13 92.17,7.67 91.82,7.67
  other vias: 92.84,7
N$X.3647  (via drill 0.2)  (1 unrouted)
  Bottom 0.2: 90.97,7 90.43,7.55 90.08,7.55
  other vias: 91.05,6.98
N$X.3648  (via drill 0.2)  (1 unrouted)
  Bottom 0.2: 89.33,7 88.79,7.55 88.44,7.55
  other vias: 89.29,6.98
N$X.3649  (via drill 0.2)  (1 unrouted)
  Bottom 0.2: 87.74,6.96 87.19,7.51 86.84,7.51
  other vias: 87.69,6.94
N$X.3650  (via drill 0.2)  (1 unrouted)
  Bottom 0.2: 85.95,7 85.41,7.55 85.06,7.55
  other vias: 85.91,6.98
N$X.3651  (via drill 0.2)  (1 unrouted)
  Bottom 0.2: 84.05,7.04 83.5,7.59 83.15,7.59
  other vias: 84,7.02
N$X.3652  (via drill 0.2)  (1 unrouted)
  Bottom 0.2: 82.22,7 81.67,7.55 81.33,7.55
  other vias: 82.09,6.94
N$X.3653  (via drill 0.2)  (1 unrouted)
  Bottom 0.2: 82.3,4.29 81.76,4.83 81.41,4.83
  other vias: 82.07,4.37
N$X.3654  (via drill 0.2)  (1 unrouted)
  Bottom 0.2: 80.48,4.37 79.93,4.91 79.58,4.91
  other vias: 80.37,4.33
N$X.3655  (via drill 0.2)  (1 unrouted)
  Bottom 0.2: 84.05,4.33 83.5,4.87 83.15,4.87
  other vias: 84,4.31
N$X.3656  (via drill 0.2)  (1 unrouted)
  Bottom 0.2: 85.89,4.33 85.35,4.87 85,4.87
  other vias: 85.91,4.33
N$X.3657  (via drill 0.2)  (1 unrouted)
  Bottom 0.2: 87.59,4.41 87.05,4.96 86.7,4.96
  other vias: 87.63,4.29
N$X.3658  (via drill 0.2)  (1 unrouted)
  Bottom 0.2: 89.42,4.39 88.87,4.93 88.52,4.93
  other vias: 89.37,4.31
N$X.3659  (via drill 0.2)  (1 unrouted)
  Bottom 0.2: 91.14,4.39 90.59,4.93 90.24,4.93
  other vias: 91.09,4.31
N$X.3660  (via drill 0.2)  (1 unrouted)
  Bottom 0.2: 92.88,4.45 92.34,5 91.99,5
  other vias: 92.84,4.35
N$X.3661  (via drill 0.2)  (1 unrouted)
  Bottom 0.2: 94.56,4.39 94.02,4.93 93.67,4.93
  other vias: 94.56,4.33
N$X.3662  (via drill 0.2)  (1 unrouted)
  Bottom 0.2: 96.34,4.41 95.8,4.96 95.45,4.96
  other vias: 96.3,4.39
N$X.3663  (via drill 0.2)  (2 unrouted)
  Top 0.8: 96.38,1.74 96.38,84.97
  Bottom 0.2: 96.39,1.69 95.84,2.24 95.49,2.24
  other vias: 96.34,1.74
N$X.3664  (via drill 0.2)  (2 unrouted)
  Top 0.8: 94.62,1.75 94.7,84.97
  Bottom 0.2: 94.66,1.71 94.12,2.26 93.77,2.26
  other vias: 94.6,1.76
N$X.3665  (via drill 0.2)  (2 unrouted)
  Top 0.8: 92.93,84.96 92.93,1.74 92.92,1.74
  Bottom 0.2: 92.98,1.71 92.44,2.26 92.09,2.26
  other vias: 92.94,1.7
N$X.3666  (via drill 0.2)  (2 unrouted)
  Top 0.8: 91.08,1.73 91.08,84.99 91.16,84.99
  Bottom 0.2: 91.16,1.73 90.61,2.28 90.27,2.28
  other vias: 91.07,1.74
N$X.3667  (via drill 0.2)  (2 unrouted)
  Top 0.8: 89.37,85.01 89.37,1.75 89.4,1.75
  Bottom 0.2: 89.25,1.78 88.71,2.32 88.36,2.32
  other vias: 89.44,1.72
N$X.3668  (via drill 0.2)  (2 unrouted)
  Top 0.8: 87.58,1.73 87.58,84.94 87.61,84.94
  Bottom 0.2: 87.47,1.76 86.92,2.3 86.57,2.3
  other vias: 87.61,1.74
N$X.3669  (via drill 0.2)  (2 unrouted)
  Top 0.8: 85.9,1.73 85.9,84.96
  Bottom 0.2: 85.79,1.73 85.24,2.28 84.89,2.28
  other vias: 85.85,1.76
N$X.3670  (via drill 0.2)  (2 unrouted)
  Top 0.8: v83.98,1.73 84.19,1.73 84.19,84.99
  Bottom 0.2: 83.84,1.71 83.29,2.26 82.94,2.26
N$X.3671  (via drill 0.2)  (1 unrouted)
  Bottom 0.2: 82.1,1.76 81.55,2.3 81.2,2.3
  other vias: 82.05,1.74
N$X.3672  (via drill 0.2)  (2 unrouted)
  Top 0.8: 80.41,1.73 80.61,1.94 80.61,84.89
  Bottom 0.2: 80.44,1.71 79.89,2.26 79.54,2.26
  other vias: 80.37,1.76
N$X.3673  (via drill 0.2)  (1 unrouted)
  Bottom 0.2: 98.09,9.62 97.54,10.16 97.19,10.16
  other vias: 98.08,9.64
N$X.3674  (via drill 0.2)  (1 unrouted)
  Bottom 0.2: 99.91,9.7 99.37,10.24 99.02,10.24
  other vias: 99.83,9.64
N$X.3675  (via drill 0.2)  (1 unrouted)
  Bottom 0.2: 101.57,9.68 101.03,10.22 100.68,10.22
  other vias: 101.53,9.66
N$X.3676  (via drill 0.2)  (1 unrouted)
  Bottom 0.2: 103.27,9.7 102.73,10.24 102.38,10.24
  other vias: 103.23,9.6
N$X.3677  (via drill 0.2)  (1 unrouted)
  Bottom 0.2: 105.06,9.64 104.51,10.18 104.16,10.18
  other vias: 105.01,9.62
N$X.3678  (via drill 0.2)  (1 unrouted)
  Bottom 0.2: 106.78,9.6 106.23,10.14 105.88,10.14
  other vias: 106.73,9.58
N$X.3679  (via drill 0.2)  (1 unrouted)
  Bottom 0.2: 108.44,9.62 107.89,10.16 107.54,10.16
  other vias: 108.39,9.6
N$X.3680  (via drill 0.2)  (1 unrouted)
  Bottom 0.2: 110.24,9.6 109.7,10.14 109.35,10.14
  other vias: 110.2,9.58
N$X.3681  (via drill 0.2)  (1 unrouted)
  Bottom 0.2: 112.03,9.6 111.48,10.14 111.13,10.14
  other vias: 111.98,9.58
N$X.3682  (via drill 0.2)  (1 unrouted)
  Bottom 0.2: 112.03,6.98 111.48,7.53 111.13,7.53
  other vias: 111.98,6.96
N$X.3683  (via drill 0.2)  (1 unrouted)
  Bottom 0.2: 110.33,6.98 109.78,7.53 109.43,7.53
  other vias: 110.28,6.96
N$X.3684  (via drill 0.2)  (1 unrouted)
  Bottom 0.2: 108.52,6.98 107.98,7.53 107.63,7.53
  other vias: 108.48,6.96
N$X.3685  (via drill 0.2)  (1 unrouted)
  Bottom 0.2: 106.78,6.96 106.23,7.51 105.88,7.51
  other vias: 106.73,6.94
N$X.3686  (via drill 0.2)  (1 unrouted)
  Bottom 0.2: 105.14,7 104.59,7.55 104.25,7.55
  other vias: 105.09,6.98
N$X.3687  (via drill 0.2)  (1 unrouted)
  Bottom 0.2: 103.38,6.96 102.83,7.51 102.48,7.51
  other vias: 103.33,6.94
N$X.3688  (via drill 0.2)  (1 unrouted)
  Bottom 0.2: 101.59,7.02 101.05,7.57 100.7,7.57
  other vias: 101.55,7
N$X.3689  (via drill 0.2)  (1 unrouted)
  Bottom 0.2: 99.89,7.02 99.35,7.57 99,7.57
  other vias: 99.85,7
N$X.3690  (via drill 0.2)  (1 unrouted)
  Bottom 0.2: 98.15,7.04 97.61,7.59 97.25,7.59
  other vias: 98.11,7.02
N$X.3691  (via drill 0.2)  (1 unrouted)
  Bottom 0.2: 98.17,4.37 97.63,4.91 97.28,4.91
  other vias: 98.13,4.35
N$X.3692  (via drill 0.2)  (1 unrouted)
  Bottom 0.2: 99.91,4.37 99.37,4.91 99.02,4.91
  other vias: 99.87,4.35
N$X.3693  (via drill 0.2)  (1 unrouted)
  Bottom 0.2: 101.68,4.37 101.13,4.91 100.78,4.91
  other vias: 101.63,4.35
N$X.3694  (via drill 0.2)  (1 unrouted)
  Bottom 0.2: 103.4,4.31 102.85,4.85 102.5,4.85
  other vias: 103.35,4.29
N$X.3695  (via drill 0.2)  (1 unrouted)
  Bottom 0.2: 104.99,4.52 104.45,5.06 104.29,4.87
  other vias: 105.14,4.31
N$X.3696  (via drill 0.2)  (1 unrouted)
  Bottom 0.2: 106.86,4.35 106.32,4.89 105.97,4.89
  other vias: 106.8,4.33
N$X.3697  (via drill 0.2)  (1 unrouted)
  Bottom 0.2: 108.4,4.33 107.85,4.87 107.5,4.87
  other vias: 108.45,4.31
N$X.3698  (via drill 0.2)  (1 unrouted)
  Bottom 0.2: 110.33,4.37 109.78,4.91 109.43,4.91
  other vias: 110.28,4.35
N$X.3699  (via drill 0.2)  (1 unrouted)
  Bottom 0.2: 111.98,4.35 111.44,4.89 111.09,4.89
  other vias: 112,4.31
N$X.3700  (via drill 0.2)  (2 unrouted)
  Top 0.8: 112.14,1.82 112.14,84.97
  Bottom 0.2: 112,1.8 111.46,2.34 111.11,2.34
  other vias: 112.01,1.77
N$X.3701  (via drill 0.2)  (1 unrouted)
  Bottom 0.2: 110.14,1.82 109.59,2.36 109.24,2.36
  other vias: 110.09,1.8
N$X.3702  (via drill 0.2)  (2 unrouted)
  Top 0.8: 108.43,1.73 108.61,1.91 108.61,84.95
  Bottom 0.2: 108.4,1.8 107.85,2.34 107.5,2.34
  other vias: 108.45,1.74
N$X.3703  (via drill 0.2)  (2 unrouted)
  Top 0.8: 106.93,84.98 106.93,1.69 106.84,1.69
  Bottom 0.2: 106.8,1.78 106.25,2.32 105.9,2.32
  other vias: 106.75,1.74
N$X.3704  (via drill 0.2)  (2 unrouted)
  Top 0.8: 104.96,1.73 105.18,1.73 105.18,84.97 105.18,84.98
  Bottom 0.2: 105.02,1.8 104.49,2.29 104.12,2.34
  other vias: 104.97,1.78
N$X.3705  (via drill 0.2)  (2 unrouted)
  Top 0.8: 103.48,84.97 103.48,1.87 103.38,1.77
  Bottom 0.2: 103.25,1.88 102.71,2.43 102.4,2.38
  other vias: 103.29,1.74
N$X.3706  (via drill 0.2)  (2 unrouted)
  Top 0.8: 101.62,1.74 101.62,84.93
  Bottom 0.2: 101.59,1.73 101.05,2.28 100.7,2.28
  other vias: 101.61,1.71
N$X.3707  (via drill 0.2)  (2 unrouted)
  Top 0.8: 99.83,1.78 99.83,84.97
  Bottom 0.2: 99.85,1.8 99.31,2.34 98.96,2.34
  other vias: 99.81,1.78
N$X.3708  (via drill 0.2)  (2 unrouted)
  Top 0.8: 98.18,1.74 98.18,84.91
  Bottom 0.2: 98.19,1.78 97.65,2.32 97.3,2.32
  other vias: 98.15,1.76
N$X.3713  (via drill 0.2)  (2 unrouted)
  Top 0.8: 3.43,1.68 3.49,1.73 3.49,84.95
  Bottom 0.2: 3.51,1.78 2.96,2.32 2.61,2.32
  other vias: 3.46,1.76
N$X.3714  (via drill 0.2)  (2 unrouted)
  Top 0.8: 5.3,84.95 5.14,84.79 v5.14,1.73
  Bottom 0.2: 5.19,1.76 4.64,2.3 4.29,2.3
N$X.3715  (via drill 0.2)  (2 unrouted)
  Top 0.8: 6.91,1.73 7.17,1.99 7.17,85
